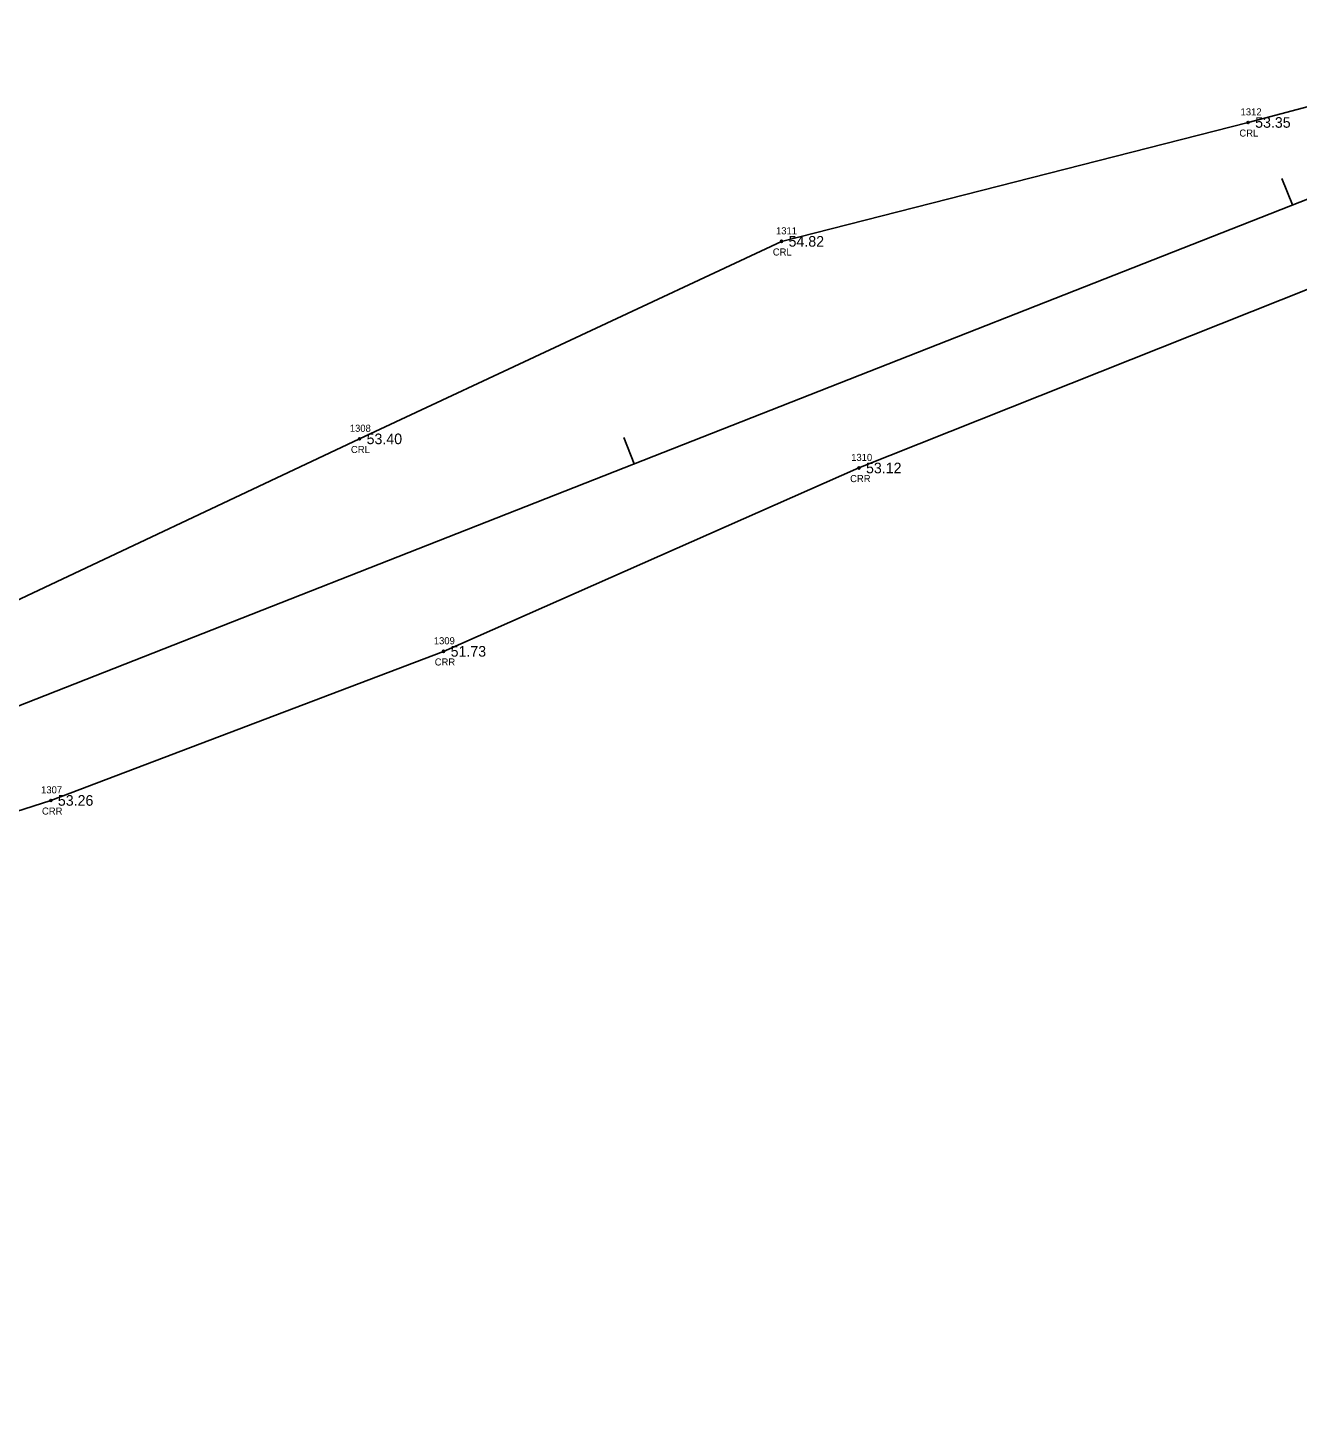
# Model space of a CAD drawing. Extents: x 2396531 to 2397633, y 770203 to 772837.
# Drawn here: x 2397236.4 to 2397415.9, y 771351.6 to 771549.6 of the extents above; entities that cross this region are included whole.
import ezdxf

# ---------------------------------------------------------------- set-up
doc = ezdxf.new("R2010")
doc.units = 0
for name, color, linetype in [('RD_EX_H2O', 7, 'Continuous'), ('RD_EX_H2O_txCode', 7, 'Continuous'), ('RD_EX_TX_H2O_ELEV', 7, 'Continuous'), ('RD_HC_Cl', 7, 'Continuous'), ('RD_HC_Data_Tic', 7, 'Continuous'), ('RD_SMD_Locator', 7, 'Continuous')]:
    doc.layers.add(name, color=color, linetype=linetype)

msp = doc.modelspace()

# ---------------------------------------------------------------- linework, layer by layer
at = {"layer": 'RD_EX_H2O'}
for points in [[(2397026.41, 771393.39), (2397070.16, 771405.14), (2397085.18, 771412.94), (2397115.64, 771424.52), (2397174.69, 771450.34), (2397230.25, 771466.48), (2397283.24, 771491.48), (2397342.91, 771519.42), (2397408.89, 771536.24), (2397447.46, 771546.47), (2397469.5, 771549.6), (2397497.19, 771541.27), (2397541.1, 771500.79)], [(2397041.52, 771355.95), (2397076.78, 771367.04), (2397074.45, 771374.78), (2397101.55, 771387.62), (2397127, 771397.33), (2397184.13, 771422.52), (2397239.58, 771440.33), (2397295.12, 771461.42), (2397353.86, 771487.36), (2397417.93, 771512.91), (2397437.51, 771516.93), (2397483.94, 771516.4), (2397526.36, 771480.62)]]:
    msp.add_lwpolyline(points, dxfattribs=at)
at = {"layer": 'RD_HC_Cl'}
msp.add_line((2396577.63, 771195.09), (2397449.32, 771538.02), dxfattribs=at)
at = {"layer": 'RD_HC_Data_Tic'}
for p, q in [((2397415.15, 771524.58), (2397413.68, 771528.3)), ((2397322.09, 771487.97), (2397320.62, 771491.69))]:
    msp.add_line(p, q, dxfattribs=at)
at = {"layer": 'RD_SMD_Locator'}
for centre in [(2397408.89, 771536.24), (2397342.91, 771519.42), (2397283.24, 771491.48), (2397353.86, 771487.36), (2397295.12, 771461.42), (2397239.58, 771440.33)]:
    msp.add_circle(centre, 0.15, dxfattribs=at)

# ---------------------------------------------------------------- texts
at = {"layer": 'RD_EX_H2O_txCode'}
for s, p in [('1312', (2397407.83, 771537.24)), ('CRL', (2397407.66, 771534.24)), ('1311', (2397342.13, 771520.42)), ('CRL', (2397341.68, 771517.42)), ('1308', (2397281.86, 771492.48)), ('CRL', (2397282.02, 771489.48)), ('1310', (2397352.76, 771488.36)), ('CRR', (2397352.61, 771485.36)), ('1309', (2397293.74, 771462.42)), ('CRR', (2397293.87, 771459.42)), ('1307', (2397238.2, 771441.33)), ('CRR', (2397238.33, 771438.33))]:
    msp.add_text(s, height=1, dxfattribs=at).set_placement(p)
at = {"layer": 'RD_EX_TX_H2O_ELEV'}
for s, p in [('53.35', (2397409.89, 771535.49)), ('54.82', (2397343.91, 771518.67)), ('53.40', (2397284.24, 771490.73)), ('53.12', (2397354.86, 771486.61)), ('51.73', (2397296.12, 771460.67)), ('53.26', (2397240.58, 771439.58))]:
    msp.add_text(s, height=1.5, dxfattribs=at).set_placement(p)

doc.saveas('drawing.dxf')
